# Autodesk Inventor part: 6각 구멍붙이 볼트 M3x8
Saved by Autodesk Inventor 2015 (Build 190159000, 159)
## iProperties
Created: 2026-09
Part Number: 6각 구멍붙이 볼트 M3x8
Material: 일반
Document SubType Name: Modeling
Designer: SCD-A06
Density: 1 g/cm^3
Appearance: 기본값
Author: SCD-A06
Author: jhkim
Description: 6각 소켓 머리 캡 나사
Creation Date: 2026-08-27
Sending System: Autodesk Inventor 2027
Preprocessor: ST-DEVELOPER v20.1
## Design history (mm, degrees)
node "6각 구멍붙이 볼트 M3x81"
body "Solid1"
node "기준1"
